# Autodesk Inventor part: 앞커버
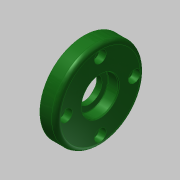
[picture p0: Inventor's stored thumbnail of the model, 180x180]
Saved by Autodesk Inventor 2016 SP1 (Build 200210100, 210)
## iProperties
Created: 2015-11
Part Number: 앞커버
Material: 알루미늄 6061
Document SubType Name: Modeling
Designer: mduedu
Density: 1 g/cm^3
Appearance: 매끄러움 - 짙은 산림 녹색
Author: mduedu
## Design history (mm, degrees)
sketch "스케치5"
  geometry: C1 r 30 at (0, 0); 2 further points
  constraints: 2 coincident, 1 centre point
  dimensions: "d66" = 60 diameter of C1
extrude "돌출2" new body sketch "스케치5" distance "d67" = 11; taper "d68" = 0 deg
sketch "스케치6"
  geometry: C1 r 16 at (0, 0); 1 further point
  constraints: 1 centre point, 1 coincident
  dimensions: "d69" = 32 diameter of C1
extrude "돌출3" join sketch "스케치6" distance "d70" = 3; taper "d71" = 0 deg
hole "구멍7" diameter "d98" = 25; stored, may be unused: countersink angle "d102" = 90 deg, drill point angle "d104" = 0 deg; dims "d96" = 10, "d97" = 10, "d99" = 6, "d100" = 4, "d101" = 2, "d103" = 3
hole "구멍8" diameter "d107" = 25; stored, may be unused: countersink angle "d111" = 90 deg, drill point angle "d113" = 0 deg; dims "d108" = 6, "d109" = 4, "d110" = 2, "d112" = 7.3, "d143" = 10, "d144" = 10
hole "구멍9" diameter "d116" = 17; stored, may be unused: countersink angle "d120" = 90 deg, drill point angle "d122" = 0 deg; dims "d114" = 10, "d115" = 10, "d117" = 6, "d118" = 4, "d119" = 2, "d121" = 7.7
chamfer "모따기2" distance "d123" = 0.7; stored, may be unused: second distance "d124" = 2, angle "d125" = 30 deg
fillet "모깎기11" dims "d126" = 0.3
fillet "모깎기13" dims "d128" = 3
fillet "모깎기14" dims "d129" = 3
fillet "모깎기15" dims "d130" = 0.3
sketch "스케치8" dims "d131" = 46
  geometry: 3 further points
  constraints: 2 vertical alignment, 1 coincident, 2 other
hole "구멍10" sketch "스케치8" at (0, 23) diameter "d132" = 4.5; stored, may be unused: countersink angle "d136" = 90 deg, drill point angle "d138" = 0 deg; dims "d133" = 6, "d134" = 8, "d135" = 4.6, "d137" = 7.7
node "솔리드2"
pattern_circular "원형 패턴4" dims angle "d140" = 360 deg
